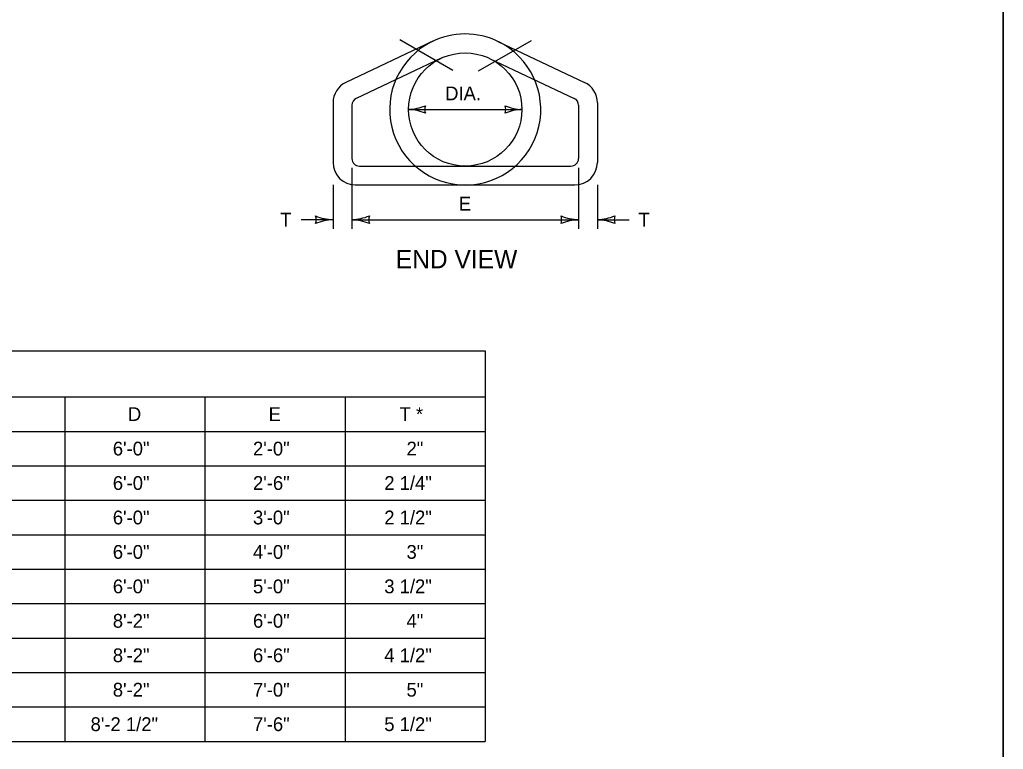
# Model space of a CAD drawing. Extents: x 49991.4 to 50021, y 49987.6 to 50011.4.
# Drawn here: x 50012.469 to 50016.75, y 49992.942 to 49996.12 of the extents above; entities that cross this region are included whole.
import ezdxf

# ---------------------------------------------------------------- set-up
doc = ezdxf.new("R2010")
doc.units = 0
for name, color, linetype in [('Level 1', 7, 'Continuous'), ('Level 2', 7, 'Continuous'), ('Level 3', 7, 'Continuous'), ('Level 4', 7, 'Continuous'), ('Level 5', 7, 'Continuous')]:
    doc.layers.add(name, color=color, linetype=linetype)

msp = doc.modelspace()

# ---------------------------------------------------------------- linework, layer by layer
at = {"layer": 'Level 1'}
for p, q in [((50014.2677, 49996.0258), (50013.8895, 49995.8466)), ((50014.5503, 49996.0252), (50014.9274, 49995.8466)), ((50014.303, 49995.9514), (50013.934, 49995.7767)), ((50014.5147, 49995.9507), (50014.8828, 49995.7765)), ((50013.8331, 49995.7574), (50013.8331, 49995.4962)), ((50013.9152, 49995.747), (50013.9152, 49995.5149)), ((50014.9015, 49995.7467), (50014.9015, 49995.5149)), ((50014.9837, 49995.7574), (50014.9837, 49995.4984)), ((50013.9482, 49995.482), (50014.8687, 49995.482)), ((50013.9294, 49995.3998), (50014.8851, 49995.3998))]:
    msp.add_line(p, q, dxfattribs=at)
msp.add_lwpolyline([(49999.3835, 49998.9992), (50016.7501, 49998.9992), (50016.7501, 49987.7988), (49999.3835, 49987.7988)], close=True, dxfattribs=at)
msp.add_circle((50014.4084, 49995.7285), 0.2466, dxfattribs=at)
for centre, radius, start, end in [((50014.4084, 49995.7285), 0.3288, 63.781, 116.8033), ((50013.9317, 49995.7574), 0.0986, 115.3382, 180), ((50014.8851, 49995.7574), 0.0986, 0, 64.6616), ((50013.9481, 49995.747), 0.0329, 115.3436, 180), ((50014.8687, 49995.7467), 0.0329, 0, 64.6714), ((50013.9317, 49995.4984), 0.0986, 180, 270), ((50013.9481, 49995.5148), 0.0329, 180, 270), ((50014.8686, 49995.5148), 0.0329, 270.1112, 0.1112), ((50014.8851, 49995.4984), 0.0986, 270, 0)]:
    msp.add_arc(centre, radius, start, end, dxfattribs=at)
at = {"layer": 'Level 2'}
for p, q in [((50016.7501, 49987.7988), (50016.7501, 49998.9992)), ((50009.6159, 49994.677), (50014.4959, 49994.677)), ((50014.4959, 49994.677), (50014.4959, 49992.977)), ((50009.6159, 49994.477), (50014.4959, 49994.477)), ((50012.6659, 49994.477), (50012.6659, 49992.977)), ((50013.2759, 49994.477), (50013.2759, 49992.977)), ((50013.8859, 49994.477), (50013.8859, 49992.977)), ((50009.6159, 49994.327), (50014.4959, 49994.327)), ((50009.6159, 49994.177), (50014.4959, 49994.177)), ((50009.6159, 49994.027), (50014.4959, 49994.027)), ((50009.6159, 49993.877), (50014.4959, 49993.877)), ((50009.6159, 49993.727), (50014.4959, 49993.727)), ((50009.6159, 49993.577), (50014.4959, 49993.577)), ((50009.6159, 49993.427), (50014.4959, 49993.427)), ((50009.6159, 49993.277), (50014.4959, 49993.277)), ((50009.6159, 49993.127), (50014.4959, 49993.127)), ((50009.6159, 49992.977), (50014.4959, 49992.977))]:
    msp.add_line(p, q, dxfattribs=at)
at = {"layer": 'Level 3'}
for p, q in [((50014.1618, 49995.7286), (50014.655, 49995.7286)), ((50013.9152, 49995.4748), (50013.9152, 49995.2086)), ((50014.9015, 49995.4748), (50014.9015, 49995.2086)), ((50013.8331, 49995.3998), (50013.8331, 49995.2086)), ((50014.9838, 49995.3998), (50014.9838, 49995.2086)), ((50013.8331, 49995.2486), (50013.6948, 49995.2486)), ((50013.9152, 49995.2486), (50014.9015, 49995.2486)), ((50014.9838, 49995.2486), (50015.1221, 49995.2486))]:
    msp.add_line(p, q, dxfattribs=at)
for centre, radius, start, end in [((50014.1508, 49995.952), 0.2237, 272.8273, 292.0772), ((50014.2849, 49995.7286), 0.0526, 162.1388, 197.8612), ((50014.6638, 49995.9418), 0.2134, 247.456, 267.6395), ((50014.5319, 49995.7286), 0.0526, 342.1388, 17.8612), ((50014.1531, 49995.5154), 0.2134, 67.456, 87.6395), ((50014.666, 49995.5052), 0.2237, 92.8273, 112.0772), ((50013.8423, 49995.4707), 0.2223, 247.456, 267.6395), ((50013.7049, 49995.2486), 0.0548, 342.1388, 17.8612), ((50013.8446, 49995.0159), 0.233, 92.8273, 112.0772), ((50013.9037, 49995.4813), 0.233, 272.8273, 292.0772), ((50013.906, 49995.0265), 0.2223, 67.456, 87.6395), ((50014.0434, 49995.2486), 0.0548, 162.1388, 197.8612), ((50014.9107, 49995.4707), 0.2223, 247.456, 267.6395), ((50014.7733, 49995.2486), 0.0548, 342.1388, 17.8612), ((50014.913, 49995.0159), 0.233, 92.8273, 112.0772), ((50014.9723, 49995.4813), 0.233, 272.8273, 292.0772), ((50014.9746, 49995.0265), 0.2223, 67.456, 87.6395), ((50015.112, 49995.2486), 0.0548, 162.1388, 197.8612)]:
    msp.add_arc(centre, radius, start, end, dxfattribs=at)
at = {"layer": 'Level 4'}
msp.add_arc((50014.4084, 49995.7285), 0.3288, 116.9522, 63.6963, dxfattribs=at)
at = {"layer": 'Level 5'}
for p, q in [((50014.354, 49995.899), (50014.1236, 49996.0323)), ((50014.4663, 49995.8967), (50014.6968, 49996.0296))]:
    msp.add_line(p, q, dxfattribs=at)

# ---------------------------------------------------------------- texts
at = {"layer": 'Level 2'}
for s, height, p in [('DIA.', 0.06, (50014.3211, 49995.7686)), ('E', 0.06, (50014.3804, 49995.2886)), ('T', 0.06, (50013.6028, 49995.2186)), ('T', 0.06, (50015.1621, 49995.2186)), ('END VIEW', 0.08, (50014.1061, 49995.037)), ('D', 0.06, (50012.9406, 49994.372)), ('E', 0.06, (50013.5529, 49994.372)), ('T *', 0.06, (50014.1227, 49994.372)), ('6\'-0"', 0.06, (50012.8748, 49994.222)), ('2\'-0"', 0.06, (50013.4848, 49994.222)), ('2"', 0.06, (50014.1529, 49994.222)), ('6\'-0"', 0.06, (50012.8748, 49994.072)), ('2\'-6"', 0.06, (50013.4848, 49994.072)), ('2 1/4"', 0.06, (50014.0562, 49994.072)), ('6\'-0"', 0.06, (50012.8748, 49993.922)), ('3\'-0"', 0.06, (50013.4848, 49993.922)), ('2 1/2"', 0.06, (50014.0562, 49993.922)), ('6\'-0"', 0.06, (50012.8748, 49993.772)), ('4\'-0"', 0.06, (50013.4848, 49993.772)), ('3"', 0.06, (50014.1529, 49993.772)), ('6\'-0"', 0.06, (50012.8748, 49993.622)), ('5\'-0"', 0.06, (50013.4848, 49993.622)), ('3 1/2"', 0.06, (50014.0562, 49993.622)), ('8\'-2"', 0.06, (50012.8748, 49993.472)), ('6\'-0"', 0.06, (50013.4848, 49993.472)), ('4"', 0.06, (50014.1529, 49993.472)), ('8\'-2"', 0.06, (50012.8748, 49993.322)), ('6\'-6"', 0.06, (50013.4848, 49993.322)), ('4 1/2"', 0.06, (50014.0562, 49993.322)), ('8\'-2"', 0.06, (50012.8748, 49993.172)), ('7\'-0"', 0.06, (50013.4848, 49993.172)), ('5"', 0.06, (50014.1529, 49993.172)), ('8\'-2 1/2"', 0.06, (50012.7781, 49993.022)), ('7\'-6"', 0.06, (50013.4848, 49993.022)), ('5 1/2"', 0.06, (50014.0562, 49993.022))]:
    msp.add_text(s, height=height, dxfattribs=at).set_placement(p)

doc.saveas('drawing.dxf')
